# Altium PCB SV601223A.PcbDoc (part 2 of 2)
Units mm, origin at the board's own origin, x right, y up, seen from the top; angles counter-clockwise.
Board outline 162.56 x 88.9 mm, 2 copper layers (Top Layer, Bottom Layer), stack 1.554 mm thick; 111 components, 38 nets, 197 pads, 254 vias.
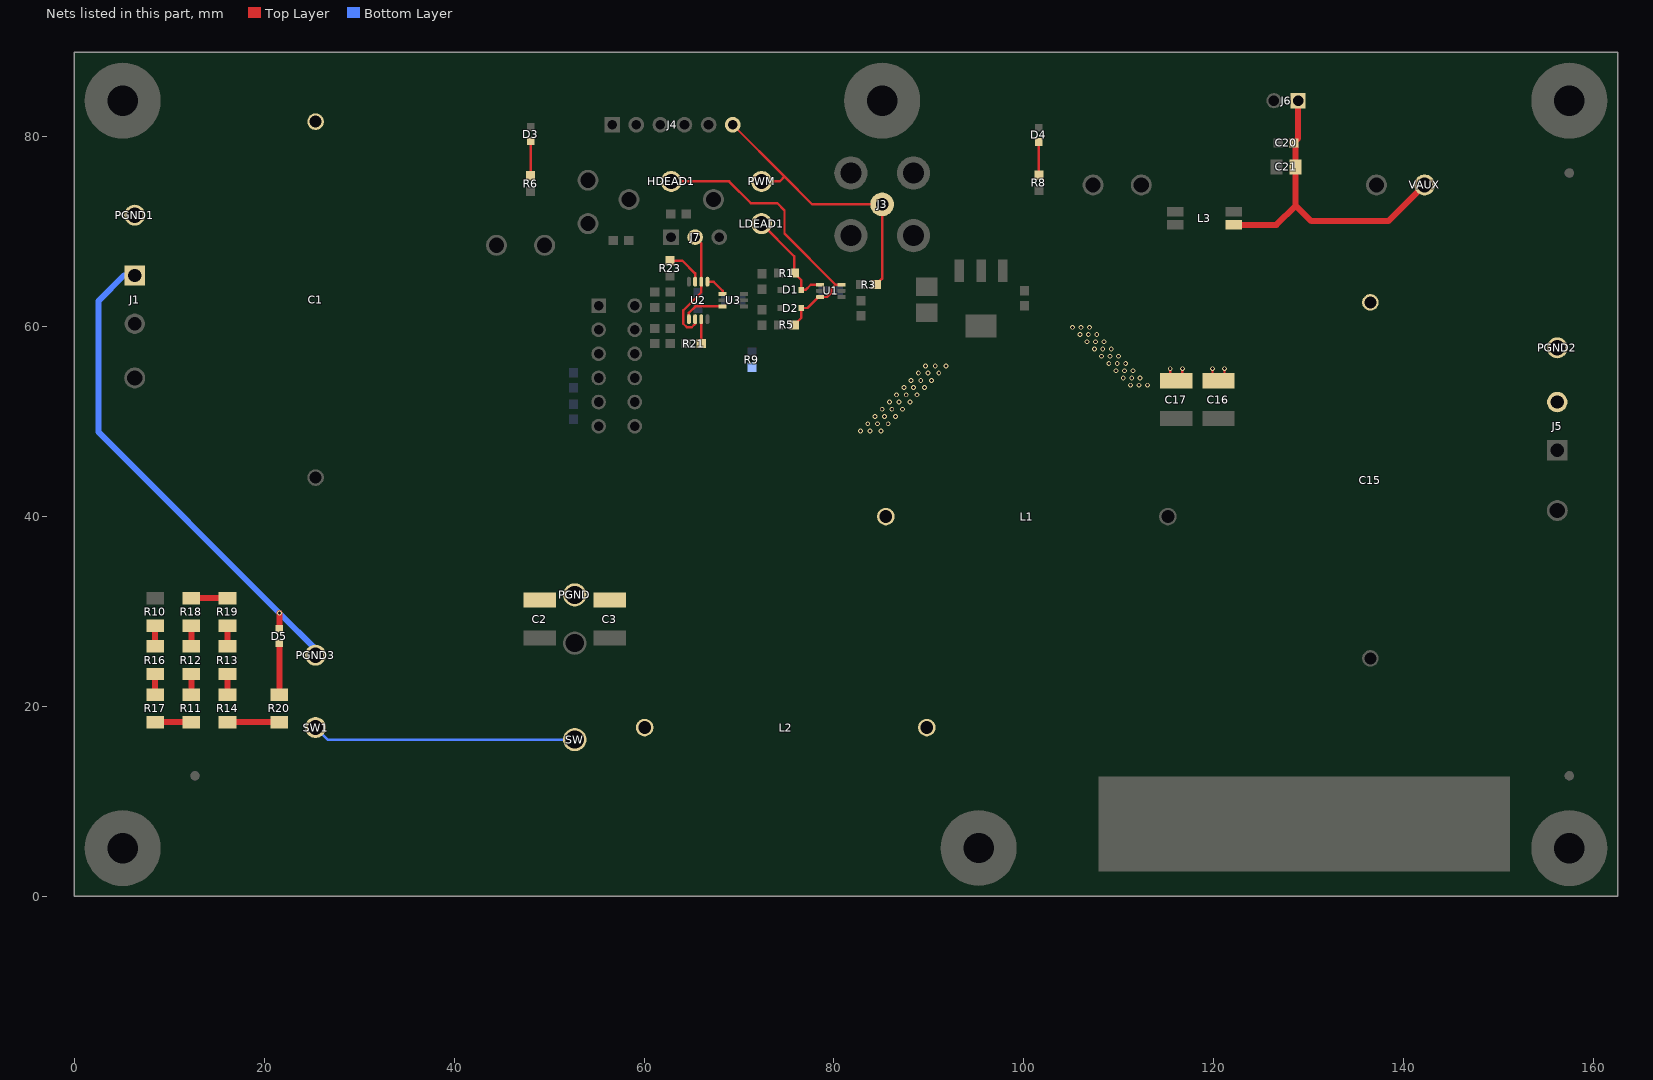
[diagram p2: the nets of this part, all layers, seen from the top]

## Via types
v1: diameter 0.508, hole 0.305, Top Layer to Bottom Layer, 254 vias

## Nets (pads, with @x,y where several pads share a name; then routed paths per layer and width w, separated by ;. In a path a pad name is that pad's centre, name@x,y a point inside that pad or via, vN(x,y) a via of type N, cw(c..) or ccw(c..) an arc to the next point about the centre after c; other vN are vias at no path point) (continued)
NetC20_2: C20.2 C21.1 J6.1 L3.3 VAUX.1 | length 34.6
  Top Layer w0.635: L3.3@122.121,70.744 126.624,70.744 128.651,72.771 ; J6.1@128.905,83.82 128.905,79.845 C20.2@128.435,79.375 128.651,79.159 C21.1@128.651,76.835 128.651,72.771 ; VAUX.1@142.237,74.943 138.414,71.12 130.302,71.12 128.651,72.771
NetD1_2: D1.2 LDEAD1.1 R1.1 U1.4 | length 10.9
  Top Layer w0.254: LDEAD1.1@72.39,70.866 75.82,67.436 R1.1@75.82,65.659 76.565,64.914 D1.2@76.565,63.881 77.02,63.881 77.574,64.435 U1.4@78.563,64.435
NetD2_2: D2.2 HDEAD1.1 R5.1 U1.3 U1.6 | length 30.8
  Top Layer w0.254: HDEAD1.1@62.865,75.311 68.961,75.311 71.247,73.025 74.041,73.025 74.803,72.263 74.803,69.815 80.183,64.435 ; R5.1@75.82,60.198 76.565,60.943 D2.2@76.565,61.976 77.216,61.976 78.375,63.135 U1.6@78.563,63.135 79.264,63.135 79.756,63.627 79.756,64.008 80.183,64.435 ; U1.3@80.813,64.435 80.183,64.435
NetD3_2: D3.2 R6.2 | length 3.7
  Top Layer w0.254: R6.2@48.068,75.89 D3.2@48.068,79.544
NetD4_1: D4.1 R8.1 | length 3.5
  Top Layer w0.254: R8.1@101.6,75.99 D4.1@101.6,79.52
NetD5_1: D5.1 R20.1 | length 5.4
  Top Layer w0.635: R20.1@21.59,21.25 D5.1@21.59,26.67
NetJ3_1: J3.1 J4.6 PWM.1 R3.2 | length 30.6
  Top Layer w0.254: J4.6@69.342,81.28 74.803,75.819 ; PWM.1@72.39,75.311 74.295,75.311 74.803,75.819 ; R3.2@84.455,64.435 85.09,65.07 J3.1@85.09,72.898 77.724,72.898 74.803,75.819
NetJ7_2: J7.2 U2.2 U2.6 | length 12.2
  Top Layer w0.254: J7.2@65.38,69.444 66.035,68.788 U2.2@66.035,64.747 66.035,63.622 64.135,61.722 64.135,60.325 64.516,59.944 65.024,59.944 65.385,60.305 U2.6@65.385,60.797
NetL1_2: L1.2 L2.1
NetL2_2: L2.2 SW1.1 SW.1 | length 27.8
  Bottom Layer w0.254: SW1.1@25.4,17.78 26.67,16.51 SW.1@52.705,16.51
NetR10_1: R10.1 R16.2 | length 2.2
  Top Layer w0.635: R16.2@8.505,26.33 R10.1@8.505,28.51
NetR11_1: R11.1 R17.2 | length 3.8
  Top Layer w0.635: R17.2@8.505,18.35 R11.1@12.315,18.35
NetR11_2: R11.2 R12.2 | length 2.2
  Top Layer w0.635: R11.2@12.315,21.25 R12.2@12.315,23.43
NetR12_1: R12.1 R18.2 | length 2.2
  Top Layer w0.635: R12.1@12.315,26.33 R18.2@12.315,28.51
NetR13_1: R13.1 R19.2 | length 2.2
  Top Layer w0.635: R13.1@16.125,26.33 R19.2@16.125,28.51
NetR13_2: R13.2 R14.2 | length 2.2
  Top Layer w0.635: R14.2@16.125,21.25 R13.2@16.125,23.43
NetR14_1: R14.1 R20.2 | length 5.5
  Top Layer w0.635: R14.1@16.125,18.35 R20.2@21.59,18.35
NetR16_1: R16.1 R17.1 | length 2.2
  Top Layer w0.635: R17.1@8.505,21.25 R16.1@8.505,23.43
NetR18_1: R18.1 R19.1 | length 3.8
  Top Layer w0.635: R18.1@12.315,31.41 R19.1@16.125,31.41
NetR21_2: R21.2 U2.7 | length 2.6
  Top Layer w0.254: R21.2@66.035,58.234 U2.7@66.035,60.797
NetR23_2: R23.2 U2.3 | length 4.1
  Top Layer w0.254: R23.2@62.751,66.954 64.059,66.954 65.385,65.628 U2.3@65.385,64.747
NetU2_1: U2.1 U3.4 | length 2.3
  Top Layer w0.254: U2.1@66.685,64.747 67.333,64.747 68.278,63.802 U3.4@68.278,63.444
NetU2_5: U2.5 U3.6 | length 4.5
  Top Layer w0.254: U2.5@64.735,60.797 64.735,61.472 65.408,62.144 U3.6@68.278,62.144
PGND: C1.2 C2.2 C3.2 C15.2 C16.2 C17.2 D5.2 J1.1 J5.2 PGND1.1 PGND2.1 PGND3.1 PGND.1 R9.2 | length 57.3
  Top Layer w0.254: C17.2@115.443,54.443 v1(115.443,55.586) ; C17.2@116.713,54.443 v1(116.713,55.586) ; C16.2@119.888,54.443 v1(119.888,55.586) ; C16.2@121.158,54.443 v1(121.158,55.586)
  Top Layer w0.635: D5.2@21.59,28.17 v1(21.59,29.845)
  Bottom Layer w0.635: J1.1@6.35,65.405 5.207,65.405 2.54,62.738 2.54,48.895 v1(21.59,29.845) PGND3.1@25.4,26.035
  other v1: 82.804,49.022 83.82,49.022 84.963,49.022 83.566,49.784 84.582,49.784 85.725,49.784 84.328,50.546 85.344,50.546 86.487,50.546 85.09,51.308 86.106,51.308 87.249,51.308 85.852,52.07 86.868,52.07 88.011,52.07 86.614,52.832 87.63,52.832 88.773,52.832 87.376,53.594 88.392,53.594 89.535,53.594 111.252,53.848 112.141,53.848 113.03,53.848 88.138,54.356 89.154,54.356 90.297,54.356 110.49,54.61 111.379,54.61 112.268,54.61 88.9,55.118 89.916,55.118 91.059,55.118 109.728,55.372 110.617,55.372 111.506,55.372 89.662,55.88 90.678,55.88 91.821,55.88 108.966,56.134 109.855,56.134 110.744,56.134 108.204,56.896 109.093,56.896 109.982,56.896 107.442,57.658 108.331,57.658 109.22,57.658 106.68,58.42 107.569,58.42 108.458,58.42 105.918,59.182 106.807,59.182 107.696,59.182 105.156,59.944 106.045,59.944 106.934,59.944
pads on no net: FID1.1 FID2.1 FID3.1 FID4.1 FID5.1 FID6.1 H1.1 H2.1 H3.1 H4.1 H9.1 H10.1 H11.0 H12.0 LBL1.0 Logo1.0 SH-J1.0

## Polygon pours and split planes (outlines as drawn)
NetC15_1 on Bottom Layer "Bottom Layer-No Net 3" (solid, remove dead copper, pour order 25): 111.76,22.86 157.48,22.86 157.48,48.26 111.76,48.26
PGND on Bottom Layer "Bottom Layer-No Net 4" (solid, remove dead copper, pour order 28): 157.48,50.8 111.76,50.8 106.68,45.72 85.09,45.72 73.66,34.29 62.23,34.29 58.344,30.404 45.796,30.404 38.735,37.465 38.735,44.45 19.304,63.881 3.81,63.881 3.81,69.215 3.81,73.025 14.605,83.82 41.275,83.82 41.275,57.15 50.464,47.961 61.169,47.961 69.418,56.21 100.508,56.21 109.702,65.405 157.48,65.405
NetC1_1 on Bottom Layer "Bottom Layer-No Net" (solid, remove dead copper, pour order 21): 3.81,62.23 3.81,50.8 35.56,19.05 46.355,19.05 50.165,22.86 55.245,22.86 58.42,26.035 58.42,28.016 45.009,28.016 36.83,36.195 36.83,43.18 19.685,60.325 17.78,62.23
NetACMGND_1 on Bottom Layer "Top Layer-No Net 1" (solid, remove dead copper, pour order 20): 121.234,66.04 121.234,85.598 135.382,85.598 144.907,76.073 144.907,66.04
AGND on Bottom Layer "Bottom Layer-No Net 5" (solid, remove dead copper, pour order 26): 116.84,66.04 109.22,66.04 100,56.82 68.758,56.82 60.579,48.641 51.054,48.641 42.164,57.531 42.164,86.36 116.84,86.36
NetL2_2 on Bottom Layer "Bottom Layer-No Net 1" (solid, remove dead copper, pour order 30): 50.8,13.97 61.595,13.97 61.595,19.05 54.61,19.05 50.8,19.05
NetL1_2 on Bottom Layer "Bottom Layer-No Net 2" (solid, remove dead copper, pour order 32): 83.82,41.91 83.82,15.875 91.44,15.875 91.44,41.91
PGND on Top Layer "Top Layer-No Net 4" (solid, remove dead copper, pour order 18): 157.48,65.405 109.855,65.405 104.775,60.325 104.775,59.69 110.947,53.518 123.139,53.518 125.857,50.8 157.48,50.8
AGND on Top Layer "Bottom Layer-No Net 5" (solid, remove dead copper, pour order 23): 116.84,66.04 109.22,66.04 100,56.82 68.758,56.82 60.579,48.641 51.054,48.641 42.164,57.531 42.164,86.36 116.84,86.36
NetC15_1 on Top Layer "Bottom Layer-No Net 3" (solid, remove dead copper, pour order 24): 111.76,22.86 157.48,22.86 157.48,49.022 124.587,49.022 122.479,51.13 114.376,51.13 111.76,48.514
PGND on Top Layer "Bottom Layer-No Net 4" (solid, remove dead copper, pour order 27): 92.659,56.21 70.739,34.29 62.23,34.29 58.344,30.404 45.796,30.404 38.735,37.465 38.735,44.45 19.304,63.881 3.81,63.881 3.81,69.215 3.81,73.025 14.605,83.82 41.275,83.82 41.275,57.15 50.464,47.961 61.169,47.961 69.418,56.21
NetC1_1 on Top Layer "Bottom Layer-No Net" (solid, remove dead copper, pour order 17): 3.81,62.23 3.81,50.8 35.56,19.05 46.355,19.05 50.165,22.86 55.245,22.86 58.42,26.035 58.42,28.016 45.009,28.016 36.83,36.195 36.83,43.18 19.685,60.325 17.78,62.23
AGND on Top Layer "Top Layer-No Net" (solid, remove dead copper, pour order 22): 88.646,60.198 88.646,63.5 91.186,63.5 92.202,62.484 95.504,62.484 95.504,61.468 92.202,61.468 91.694,60.96 91.694,60.198
NetACMGND_1 on Top Layer "Top Layer-No Net 1" (solid, remove dead copper, pour order 19): 121.234,66.04 121.234,85.598 135.382,85.598 144.907,76.073 144.907,66.04
NetL2_2 on Top Layer "Top Layer-No Net 2" (solid, remove dead copper, pour order 29): 50.8,19.05 61.595,19.05 61.595,13.97 50.8,13.97
NetL1_2 on Top Layer "Top Layer-No Net 3" (solid, remove dead copper, pour order 31): 83.82,41.91 83.82,15.875 91.44,15.875 91.44,41.91

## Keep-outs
Keep-Out Layer:
  lines w0.1: -0.05,0 ccw(c0,0) 0,-0.05 ; -0.05,0 ccw(c0,0) 0,-0.05 ; -0.05,0 -0.05,88.9 ; -0.05,88.9 cw(c0,88.9) 0,88.95 ; -0.05,88.9 cw(c0,88.9) 0,88.95 ; 0,-0.05 162.56,-0.05 ; 0,88.95 162.56,88.95 ; 162.56,-0.05 ccw(c162.56,0) 162.61,0 ; 162.56,-0.05 ccw(c162.56,0) 162.61,0 ; 162.56,88.95 cw(c162.56,88.9) 162.61,88.9 ; 162.56,88.95 cw(c162.56,88.9) 162.61,88.9 ; 162.61,0 162.61,88.9
  text ".Layer_Name" at 14.656,-21.806 h1.52

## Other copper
Top Layer:
  text ".Layer_Name" at 14.656,-21.806 h1.52
Bottom Layer:
  text ".Layer_Name" at 14.656,-21.806 h1.52

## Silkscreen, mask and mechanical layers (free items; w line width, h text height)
Top Overlay:
  region: 143.535,17.094 135.915,17.094 135.915,14.554 143.535,14.554
  lines w0.152: 41.275,15.24 41.275,12.7 57.785,12.7 57.785,15.24 ; 41.275,62.23 41.275,64.77 57.785,64.77 57.785,62.23
  text "- 12V AUX +" at 122.555,87.63 h1.02
  text "FAULT" at 57.023,83.312 h1.02 r90
  text "GND" at 59.563,83.312 h1.02 r90
  text "LOW" at 62.103,83.312 h1.02 r90
  text "HIGH" at 64.643,83.312 h1.02 r90
  text "GND" at 67.183,83.312 h1.02 r90
  text "PWM" at 69.723,83.312 h1.02 r90
  text "AUX ENABLE" at 97.028,82.55 h1.02
  text "FAULT" at 45.72,82.042 h1.02
  text "PWM INPUT" at 91.567,70.104 h1.02
  text "FAULT" at 53.34,67.056 h1.02
  text "EN" at 59.885,66.891 h1.02
  text "|" at 65.405,66.802 h1.02
  text "DIS" at 66.802,66.802 h1.02
  text "- VIN +" at 0.508,66.548 h1.02 r270
  text "Protect" at 52.578,65.659 h1.02
  text "HIGH" at 49.445,61.722 h1.02
  text "LOW" at 50.291,59.182 h1.02
  text "FAULT" at 48.26,56.642 h1.02
  text "5V" at 51.307,54.102 h1.02
  text "12V" at 50.461,51.562 h1.02
  text "AGND" at 49.149,49.403 h1.02
  text "+ VOUT -" at 162.052,45.847 h1.02 r90
  text "HV" at 20.701,32.385 h1.02
  text "Enable" at 19.05,30.48 h1.02
  text "Caution" at 31.369,24.13 h1.52
  text "High Voltage" at 27.94,21.717 h1.52
  text "Op V:480V" at 29.21,19.05 h1.52
  text ".PRJ_Number" at 117.246,15.062 h1.52
  text ".PCB_Rev" at 131.343,15.062 h1.52
  text "-" at 134.137,15.062 h1.52
  text "LMG34XX-BB-EVM" at 23.876,5.715 h1.52
  text ".Layer_Name" at 14.656,-21.806 h1.52
Bottom Overlay:
  text ".Layer_Name" at 14.656,-21.806 h1.52
Top Paste:
  text ".Layer_Name" at 14.656,-21.806 h1.52
Bottom Paste:
  text ".Layer_Name" at 14.656,-21.806 h1.52
Top Solder:
  text ".Layer_Name" at 14.656,-21.806 h1.52
  text ".Layer_Name" at 14.656,-21.806 h1.52
Bottom Solder:
  text ".Layer_Name" at 14.656,-21.806 h1.52
Drill Guide:
  text ".Layer_Name" at 14.656,-21.806 h1.52
M1 Board Outline:
  the board outline again, w0.127
  text ".Layer_Name" at 14.656,-21.806 h1.52
M2 Board Dimensions:
  rectangle: 3.175,-10.16 12.7,-6.985
  rectangle: 0,-6.985 3.175,-3.81
  lines w0.178: 0,-6.985 25.4,-6.985 ; 3.175,-10.16 3.175,-3.81 ; 6.35,-10.16 6.35,-3.81 ; 12.7,-10.16 12.7,-3.81 ; 19.05,-10.16 19.05,-3.81 ; 0,-10.16 0,-3.81 25.4,-3.81 25.4,-10.16 0,-10.16
  text ".Layer_Name" at 14.656,-21.806 h1.52
M3 3D STEP Top:
  text ".Layer_Name" at 14.656,-21.806 h1.52
M4 3D STEP Bottom:
  text ".Layer_Name" at 14.656,-21.806 h1.52
M5 Assembly Top:
  lines w0.254: -7.417,-23.626 160.223,-23.626 ; -7.417,-18.462 160.274,-18.462 ; -7.417,-13.297 -7.417,-28.791 94.31,-28.791 160.274,-28.791 160.274,-13.297 -7.404,-13.297 -7.404,-28.791 32.614,-28.791 ; 55.194,-28.791 55.194,-13.297 ; 87.376,-18.462 87.376,-13.297 ; 108.712,-18.462 108.712,-13.297 ; 124.511,-28.956 124.511,-23.804
  text "COMPONENTS MARKED 'DNP' SHOULD NOT BE POPULATED." at 29.299,-8.09 h1.52
  text "ASSEMBLY VARIANT:" at 29.286,-11.024 h1.52
  text ".VariantName" at 55.601,-11.024 h1.52
  text "PCB VIEWED FROM TOP SIDE" at -5.804,-16.654 h1.52
  text "BOARD #:" at 57.099,-16.654 h1.52
  text ".PRJ_Number" at 70.955,-16.654 h1.52
  text "REV:" at 92.405,-16.654 h1.52
  text ".PCB_Rev" at 99.809,-16.654 h1.52
  text "SVN REV:" at 113.69,-16.654 h1.52
  text ".VersionControl_RevNumber" at 126.543,-16.654 h1.52
  text "TID #:" at 57.099,-21.819 h1.52
  text ".TID" at 70.955,-21.819 h1.52
  text "PLOT NAME =" at -5.804,-27.034 h1.52
  text ".plot_File_Name" at 14.656,-27.034 h1.52
  text "GENERATED    :" at 57.15,-27.034 h1.52
  text ".Print_Date" at 79.235,-27.034 h1.52
  text ".Print_Time" at 97.752,-27.034 h1.52
  text "TEXAS INSTRUMENTS" at 129.87,-27.034 h1.52
M6 Assembly Bottom:
  lines w0.254: -7.429,-18.474 160.261,-18.474 ; -7.379,-23.639 160.261,-23.639 ; 28.334,-28.969 28.334,-23.817 ; 44.133,-18.474 44.133,-13.31 ; 65.468,-18.474 65.468,-13.31 ; 97.65,-28.804 97.65,-13.31 ; 120.231,-28.804 160.249,-28.804 160.249,-13.31 -7.429,-13.31 -7.429,-28.804 58.534,-28.804 160.261,-28.804 160.261,-13.31
  text "COMPONENTS MARKED 'DNP' SHOULD NOT BE POPULATED." at 154.991,-8.077 h1.52
  text ".VariantName" at 128.473,-11.024 h1.52
  text "ASSEMBLY VARIANT:" at 154.864,-11.024 h1.52
  text ".VersionControl_RevNumber" at 26.302,-16.667 h1.52
  text "SVN REV:" at 39.154,-16.667 h1.52
  text ".PCB_Rev" at 53.035,-16.667 h1.52
  text "REV:" at 60.439,-16.667 h1.52
  text ".PRJ_Number" at 81.89,-16.667 h1.52
  text "BOARD #:" at 95.745,-16.667 h1.52
  text "PCB VIEWED FROM BOTTOM SIDE" at 158.648,-16.667 h1.52
  text ".TID" at 81.89,-21.831 h1.52
  text "TID #:" at 95.745,-21.831 h1.52
  text "TEXAS INSTRUMENTS" at 22.974,-27.047 h1.52
  text ".Print_Time" at 55.093,-27.047 h1.52
  text ".Print_Date" at 73.609,-27.047 h1.52
  text "GENERATED    :" at 95.694,-27.047 h1.52
  text ".plot_File_Name" at 138.189,-27.047 h1.52
  text "PLOT NAME =" at 158.648,-27.047 h1.52
M9 Title Sheet:
  drawing of 57 lines, arcs and shapes, not listed
  text "1" at 18.792,204.127 h1.78
  text "2" at 82.182,204.127 h1.78
  text "3" at 145.411,204.127 h1.78
  text "4" at 209.08,204.127 h1.78
  text "5" at 272.555,204.127 h1.78
  text "6" at 336.182,204.127 h1.78
  text "A" at -10.579,175.095 h1.78
  text "A" at 365.341,175.095 h1.78
  text "B" at -10.579,114.643 h1.78
  text "B" at 365.341,114.643 h1.78
  text "C" at -10.579,54.318 h1.78
  text "C" at 365.341,54.318 h1.78
  text "PROJECT TITLE:" at 288.125,7.048 h1.14
  text ".PRJ_Title" at 289.395,3.662 h1.78
  text "DESIGNED FOR:" at 288.125,-0.597 h1.14
  text ".PRJ_Customer" at 289.395,-4.153 h1.78
  text "D" at -10.579,-5.88 h1.78
  text "D" at 365.341,-5.88 h1.78
  text "FILE NAME:" at 288.125,-8.217 h1.14
  text ".PCB_File_Name_No_Path" at 289.395,-11.265 h1.78
  text "Texas Instruments (TI) and/or its licensors do not warrant the accuracy or completeness of this specification" at 161.9,-15.376 h1.14
  text "ENGINEER:" at 288.125,-15.583 h1.14
  text "LAYOUT BY:" at 326.352,-15.583 h1.14
  text "or any information contained therein. TI and/or its licensors do not warrant that this design will meet" at 160.757,-18.237 h1.14
  text ".PRJ_Engineer" at 289.395,-19.52 h1.78
  text ".PCB_Layout" at 327.635,-19.52 h1.78
  text "the specifications, will be suitable for your application or fit for any particular purpose, or will operate in" at 160.757,-21.099 h1.14
  text ".Layer_Name" at 14.656,-21.806 h1.52
  text "ALTIUM DESIGNER VERSION:" at 326.352,-23.457 h1.14
  text "an implementation. TI and/or its licensors do not warrant that the design is production worthy. You should" at 160.757,-23.961 h1.14
  text "completely validate and test your design implementation to confirm the system functionality for your application." at 161.9,-26.822 h1.14
  text ".print_Scale" at 289.395,-26.843 h1.78
  text ".Application_BuildNumber" at 327.635,-26.843 h1.78
  text "1" at 18.792,-32.093 h1.78
  text "2" at 82.182,-32.093 h1.78
  text "3" at 145.411,-32.093 h1.78
  text "4" at 209.08,-32.093 h1.78
  text "5" at 272.555,-32.093 h1.78
  text "6" at 336.182,-32.093 h1.78
M10 Fab Notes:
  drawing of 185 lines, arcs and shapes, not listed
  text "DESIGN INFORMATION" at 314.478,150.114 h1.52
  text "MIN. TRACK WIDTH:" at 298.106,145.542 h1.52
  text "8" at 325.951,145.542 h1.52
  text "MIL" at 329.881,145.542 h1.52
  text "MIN. CLEARANCE:" at 298.106,142.189 h1.52
  text "0.2" at 324.427,142.189 h1.52
  text "mm" at 329.881,142.189 h1.52
  text "MIN. VIA PAD SIZE:" at 298.106,138.836 h1.52
  text "20" at 325.189,138.836 h1.52
  text "MIL" at 329.881,138.836 h1.52
  text "0.05mm (2MIL)" at 315.759,135.237 h1.52
  text "MINIMUM ANNULAR RING" at 289.744,135.128 h1.52
  text "EXTERNAL" at 333.742,135.128 h1.52
  text "PER" at 294.824,132.131 h1.52
  text "IPC-D-275 CLASS 2 LEVEL C" at 300.412,132.131 h1.52
  text "MIL, HOLES" at 338.213,129.279 h1.52
  text "+/-" at 328.244,129.261 h1.52
  text "+/-" at 349.936,129.261 h1.52
  text "REGISTRATION TOLERANCES:" at 289.744,129.134 h1.52
  text "METAL" at 320.218,129.134 h1.52
  text "5" at 334.853,129.134 h1.52
  text "3" at 356.012,129.134 h1.52
  text "MIL" at 358.964,129.134 h1.52
  text "MATERIAL:" at 287.844,123.813 h1.52
  text "FR-4 High Tg" at 312.9,120.249 h1.52
  text "FR-408" at 298.538,120.031 h1.52
  text "X" at 309.003,120.031 h1.52
  text "OTHER" at 336.333,120.031 h1.52
  text "62 MIL (1.6mm) +/-10%" at 306.668,115.898 h1.52
  text "THICKNESS:" at 289.744,115.789 h1.52
  text "X" at 303.413,115.789 h1.52
  text "OTHER" at 339.305,115.789 h1.52
  text "TOLERANCE:" at 289.744,111.776 h1.52
  text "X" at 311.062,111.776 h1.52
  text "ANSI IPC-6012 TYPE 3 CLASS 2" at 315.81,111.776 h1.52
  text "OTHER +/-" at 315.81,107.814 h1.52
  text "BOW & TWIST:" at 289.744,103.826 h1.52
  text "X" at 311.062,103.826 h1.52
  text "ANSI IPC-6012 TYPE 3 CLASS 2" at 315.81,103.826 h1.52
  text "OTHER +/-" at 315.81,99.8 h1.52
  text "DRILLING:" at 287.844,96.282 h1.52
  text "REFERENCE:" at 289.744,93.31 h1.52
  text "X" at 306.209,93.31 h1.52
  text "AS SHOWN" at 310.958,93.31 h1.52
  text "X" at 329.094,93.31 h1.52
  text "NC_DRILL FILES" at 332.574,93.31 h1.52
  text "PTH MIN COPPER THICKNESS:" at 289.744,89.297 h1.52
  text "X" at 323.836,89.297 h1.52
  text "1MIL" at 327.519,89.297 h1.52
  text "OTHER" at 340.143,89.297 h1.52
  text "BOARD FINISH:" at 287.844,85.259 h1.52
  text "SILKSCREEN:" at 291.787,82.261 h1.52
  text "X" at 315.886,82.261 h1.52
  text "TOP" at 319.086,82.261 h1.52
  text "X" at 328.84,82.261 h1.52
  text "BOTTOM" at 332.066,82.261 h1.52
  text "SILKSCREEN COLOR:" at 291.787,78.02 h1.52
  text "X" at 315.86,78.02 h1.52
  text "WHITE" at 319.086,78.02 h1.52
  text "OTHER" at 332.066,78.02 h1.52
  text "SOLDER RESIST COLOR:" at 291.787,73.702 h1.52
  text "X" at 306.208,69.658 h1.52
  text "GREEN" at 309.434,69.658 h1.52
  text "BLUE" at 324.446,69.658 h1.52
  text "OTHER" at 338.111,69.658 h1.52
  text "IMMERSION GOLD (ENIG)" at 314.794,64.87 h1.52
  text "ENEPIG" at 348.767,64.786 h1.52
  text "SURFACE FINISH:" at 287.844,64.761 h1.52
  text "X" at 310.045,64.761 h1.52
  text "IMM. TIN/SILVER OR EQUIV" at 296.215,60.773 h1.52
  text "OTHER" at 332.574,60.773 h1.52
  text "ARRAY/PANEL:" at 287.844,56.226 h1.52
  text "CUT AND TRIM PER MECH LAYER 1" at 314.794,56.118 h1.52
  text "N.C. ROUTE" at 314.794,52.264 h1.52
  text "X" at 332.04,52.264 h1.52
  text "V. SCORE" at 336.79,52.264 h1.52
  text "CERTIFICATION:" at 287.844,48.784 h1.52
  text "MATERIALS AND WORKMANSHIP FOR ALL PCBS" at 306.259,48.784 h1.52
  text "TO MEET OR EXCEED THE REQUIREMENTS OF:" at 306.259,46.295 h1.52
  text "X" at 296.773,42.828 h1.52
  text "ANSI IPC-A-600F CLASS ->" at 300.303,42.828 h1.52
  text "X" at 341.935,42.828 h1.52
  text "2" at 344.956,42.828 h1.52
  text "1" at 336.955,42.79 h1.52
  text "3" at 353.948,42.79 h1.52
  text "X" at 296.825,38.777 h1.52
  text "UL 94V-0" at 300.303,38.777 h1.52
  text "X" at 317.45,38.777 h1.52
  text "RoHS" at 320.928,38.777 h1.52
  text "OTHER" at 337.296,38.777 h1.52
  text "PER ORDER" at 347.381,38.777 h1.52
  text "ADDITIONAL REQUIREMENTS:" at 287.844,35.195 h1.52
  text "MICROSECTION:" at 289.744,32.274 h1.52
  text "YES" at 312.749,32.274 h1.52
  text "REQUIRED" at 334.631,28.308 h1.52
  text "BARE BOARD ELEC. TEST:" at 289.744,28.236 h1.52
  text "NONE" at 322.909,28.236 h1.52
  text "X" at 331.405,28.236 h1.52
  text "PER ORDER" at 349.668,28.236 h1.52
  text "MANUFACTURER'S UL:" at 289.744,24.248 h1.52
  text "RAIL" at 319.353,24.139 h1.52
  text "METAL" at 331.845,24.139 h1.52
  text "X" at 341.376,24.13 h1.52
  text "SILK" at 344.842,24.139 h1.52
  text ".Layer_Name" at 14.656,-21.806 h1.52
M11 Gerber Information:
  lines w0.254: -7.417,-23.626 160.223,-23.626 ; -7.417,-18.462 160.274,-18.462 ; -7.417,-13.297 -7.417,-28.791 94.31,-28.791 160.274,-28.791 160.274,-13.297 -7.404,-13.297 -7.404,-28.791 32.614,-28.791 ; 55.194,-28.791 55.194,-13.297 ; 87.376,-18.462 87.376,-13.297 ; 108.712,-18.462 108.712,-13.297 ; 124.511,-28.956 124.511,-23.804
  text "ALL ARTWORK VIEWED FROM TOP SIDE" at -5.804,-16.654 h1.52
  text "BOARD #:" at 57.099,-16.654 h1.52
  text ".PRJ_Number" at 70.955,-16.654 h1.52
  text "REV:" at 92.405,-16.654 h1.52
  text ".PCB_Rev" at 99.809,-16.654 h1.52
  text "SVN REV:" at 113.69,-16.654 h1.52
  text ".VersionControl_RevNumber" at 126.543,-16.654 h1.52
  text "LAYER NAME =" at -5.804,-21.806 h1.52
  text "TID #:" at 57.099,-21.819 h1.52
  text ".TID" at 70.955,-21.819 h1.52
  text "PLOT NAME =" at -5.804,-27.034 h1.52
  text ".plot_File_Name" at 14.656,-27.034 h1.52
  text "GENERATED    :" at 57.15,-27.034 h1.52
  text ".Print_Date" at 79.235,-27.034 h1.52
  text ".Print_Time" at 97.752,-27.034 h1.52
  text "TEXAS INSTRUMENTS" at 129.87,-27.034 h1.52
M12 Stackup:
  drawing of 191 lines, arcs and shapes, not listed
  text "Layer" at 248.865,198.882 h1.52
  text "Name" at 259.277,198.882 h1.52
  text "Material" at 282.892,198.882 h1.52
  text "Thickness" at 304.731,198.882 h1.52
  text "Constant" at 321.236,198.882 h1.52
  text "Board Layer Stack" at 335.711,198.882 h1.52
  text "1" at 248.865,195.834 h1.52
  text "Top Overlay" at 259.277,195.834 h1.52
  text "2" at 248.865,192.786 h1.52
  text "Top Solder" at 259.277,192.786 h1.52
  text "Solder Resist" at 282.892,192.786 h1.52
  text "0.40mil" at 304.731,192.786 h1.52
  text "3.5" at 321.236,192.786 h1.52
  text "3" at 248.865,189.738 h1.52
  text "Top Layer" at 259.277,189.738 h1.52
  text "Copper" at 282.892,189.738 h1.52
  text "2.80mil" at 304.731,189.738 h1.52
  text "4" at 248.865,186.69 h1.52
  text "Dielectric1" at 259.277,186.69 h1.52
  text "FR-4 High Tg" at 282.892,186.69 h1.52
  text "55.60mil" at 304.731,186.69 h1.52
  text "4.8" at 321.236,186.69 h1.52
  text "5" at 248.865,183.642 h1.52
  text "Bottom Layer" at 259.277,183.642 h1.52
  text "Copper" at 282.892,183.642 h1.52
  text "2.80mil" at 304.731,183.642 h1.52
  text "6" at 248.865,180.594 h1.52
  text "Bottom Solder" at 259.277,180.594 h1.52
  text "Solder Resist" at 282.892,180.594 h1.52
  text "0.40mil" at 304.731,180.594 h1.52
  text "3.5" at 321.236,180.594 h1.52
  text "7" at 248.865,177.546 h1.52
  text "Bottom Overlay" at 259.277,177.546 h1.52
  text ".Layer_Name" at 14.656,-21.806 h1.52
M13 Component Bodies Top:
  text ".Layer_Name" at 14.656,-21.806 h1.52
M14 Component Bodies Bottom:
  text ".Layer_Name" at 14.656,-21.806 h1.52
M15 Courtyards Top:
  text ".Layer_Name" at 14.656,-21.806 h1.52
M16 Courtyards Bottom:
  text ".Layer_Name" at 14.656,-21.806 h1.52
Drill Drawing:
  lines w0.254: 232.977,112.306 234.38,112.306 234.38,113.709 232.977,113.709 232.977,112.306 ; 232.977,118.621 233.679,118.972 234.38,118.621 234.03,119.323 234.38,120.025 233.679,119.674 232.977,120.025 233.328,119.323 232.977,118.621 ; 232.977,124.937 232.977,125.287 233.328,125.638 232.977,125.989 232.977,126.34 233.328,126.34 233.679,125.989 234.03,126.34 234.38,126.34 234.38,125.989 234.03,125.638 234.38,125.287 234.38,124.937 234.03,124.937 233.679,125.287 233.328,124.937 232.977,124.937 ; 233.258,112.586 234.1,112.586 234.1,113.428 233.258,113.428 233.258,112.586 ; 233.258,118.902 233.679,119.112 234.1,118.902 233.889,119.323 234.1,119.744 233.679,119.533 233.258,119.744 233.468,119.323 233.258,118.902 ; 233.258,125.217 233.258,125.428 233.468,125.638 233.258,125.849 233.258,126.059 233.468,126.059 233.679,125.849 233.889,126.059 234.1,126.059 234.1,125.849 233.889,125.638 234.1,125.428 234.1,125.217 233.889,125.217 233.679,125.428 233.468,125.217 233.258,125.217
  lines w0.305: 231.705,111.358 281.946,111.358 ; 231.705,149.251 281.946,149.251 ; 240.286,108.201 240.286,152.409 ; 248.719,108.201 248.719,152.409 ; 264.888,108.201 264.888,152.409 ; 271.47,108.201 271.47,152.409 ; 231.705,108.201 281.946,108.201 281.946,152.409 231.705,152.409 231.705,108.201
  text "Symbol" at 233.599,150.198 h1.83
  text "Quantity" at 241.234,150.198 h1.83
  text "Finished Hole Size" at 249.666,150.198 h1.83
  text "Plated" at 265.835,150.198 h1.83
  text "Hole Type" at 272.417,150.198 h1.83
  text "254" at 241.234,147.041 h1.52
  text "12.00mil (0.305mm)" at 249.666,147.041 h1.52
  text "PTH" at 265.835,147.041 h1.52
  text "Round" at 272.417,147.041 h1.52
  text "I" at 233.191,146.787 h1.4
  text "9" at 241.234,143.883 h1.52
  text "40.00mil (1.016mm)" at 249.666,143.883 h1.52
  text "PTH" at 265.835,143.883 h1.52
  text "Round" at 272.417,143.883 h1.52
  text "H" at 232.957,143.629 h1.4
  text "12" at 241.234,140.725 h1.52
  text "40.16mil (1.020mm)" at 249.666,140.725 h1.52
  text "PTH" at 265.835,140.725 h1.52
  text "Round" at 272.417,140.725 h1.52
  text "F" at 232.957,140.471 h1.4
  text "2" at 241.234,137.568 h1.52
  text "43.31mil (1.100mm)" at 249.666,137.568 h1.52
  text "PTH" at 265.835,137.568 h1.52
  text "Round" at 272.417,137.568 h1.52
  text "G" at 232.957,137.314 h1.4
  text "4" at 241.234,134.41 h1.52
  text "49.21mil (1.250mm)" at 249.666,134.41 h1.52
  text "PTH" at 265.835,134.41 h1.52
  text "Round" at 272.417,134.41 h1.52
  text "A" at 232.957,134.156 h1.4
  text "1" at 241.234,131.252 h1.52
  text "51.18mil (1.300mm)" at 249.666,131.252 h1.52
  text "PTH" at 265.835,131.252 h1.52
  text "Round" at 272.417,131.252 h1.52
  text "E" at 232.957,130.998 h1.4
  text "4" at 241.234,128.094 h1.52
  text "53.15mil (1.350mm)" at 249.666,128.094 h1.52
  text "PTH" at 265.835,128.094 h1.52
  text "Round" at 272.417,128.094 h1.52
  text "C" at 232.957,127.841 h1.4
  text "4" at 241.234,124.937 h1.52
  text "55.12mil (1.400mm)" at 249.666,124.937 h1.52
  text "PTH" at 265.835,124.937 h1.52
  text "Round" at 272.417,124.937 h1.52
  text "19" at 241.234,121.779 h1.52
  text "63.00mil (1.600mm)" at 249.666,121.779 h1.52
  text "PTH" at 265.835,121.779 h1.52
  text "Round" at 272.417,121.779 h1.52
  text "B" at 232.957,121.525 h1.4
  text "3" at 241.234,118.621 h1.52
  text "75.00mil (1.905mm)" at 249.666,118.621 h1.52
  text "PTH" at 265.835,118.621 h1.52
  text "Round" at 272.417,118.621 h1.52
  text "4" at 241.234,115.463 h1.52
  text "86.61mil (2.200mm)" at 249.666,115.463 h1.52
  text "PTH" at 265.835,115.463 h1.52
  text "Round" at 272.417,115.463 h1.52
  text "D" at 232.957,115.21 h1.4
  text "6" at 241.234,112.306 h1.52
  text "125.98mil (3.200mm)" at 249.666,112.306 h1.52
  text "PTH" at 265.835,112.306 h1.52
  text "Round" at 272.417,112.306 h1.52
  text "322 Total" at 241.234,109.148 h1.52
  text ".Layer_Name" at 14.656,-21.806 h1.52

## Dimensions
0,0 to 162.56,0 on M2 Board Dimensions
0,0 to 0,88.9 on M2 Board Dimensions
0,-10.16 to 25.4,-10.16 on M2 Board Dimensions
